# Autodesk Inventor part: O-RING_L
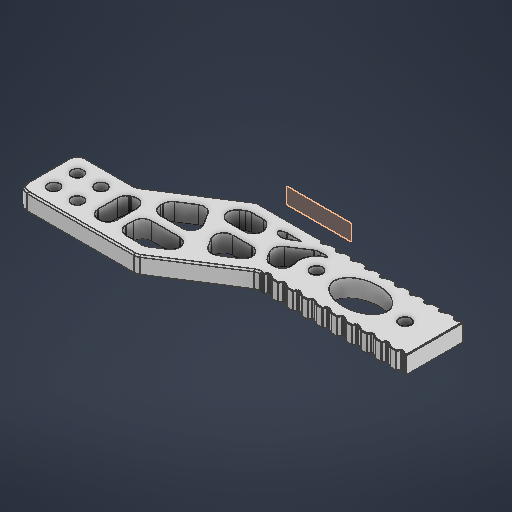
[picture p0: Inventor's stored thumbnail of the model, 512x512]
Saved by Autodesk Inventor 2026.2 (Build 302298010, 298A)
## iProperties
Created: 2026-05
Part Number: O-RING_L
Material: 일반
Document SubType Name: Modeling
Designer: work
Density: 1 g/cm^3
Appearance: 기본값
Author: work
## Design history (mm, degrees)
sketch "스케치1"
  geometry: L1 (0, 22)-(0, -22); L2 (0, -22)-(8, -22); L3 (8, -22)-(8, -30); L4 (8, -30)-(0, -30); L5 (0, -30)-(0, -22); L6 (0, -22)-(8, -30); L7 (8, -22)-(0, -30); L8 (-6, -36)-(14, -36); L9 (14, -36)-(14, -16); L10 (14, -16)-(-6, -16); L11 (-6, -16)-(-6, -36); L12 (-6, -36)-(14, -16); L13 (14, -36)-(-6, -16); L14 (-6, -16)-(-31, 0); L15 (-101, 0)-(-101, -20); L16 (-6, -36)-(-26, -36); L17 (-26, -36)-(-51, -20); L18 (0, 0)-(-31, 0); L19 (-101, -10)-(-15.375, -10); L20 (-101, 0)-(-99.268, -1); L21 (-99.268, -1)-(-98.577, -1); L22 (-98.577, -1)-(-98, 0); L23 (-93.577, -1)-(-93, 0); L24 (-94.268, -1)-(-93.577, -1); L25 (-96, 0)-(-94.268, -1); L26 (-88.577, -1)-(-88, 0); L27 (-89.268, -1)-(-88.577, -1); L28 (-91, 0)-(-89.268, -1); L29 (-83.577, -1)-(-83, 0); L30 (-84.268, -1)-(-83.577, -1); L31 (-86, 0)-(-84.268, -1); L32 (-78.577, -1)-(-78, 0); L33 (-79.268, -1)-(-78.577, -1); L34 (-81, 0)-(-79.268, -1); L35 (-73.577, -1)-(-73, 0); L36 (-74.268, -1)-(-73.577, -1); L37 (-76, 0)-(-74.268, -1); L38 (-68.577, -1)-(-68, 0); L39 (-69.268, -1)-(-68.577, -1); L40 (-71, 0)-(-69.268, -1); L41 (-63.577, -1)-(-63, 0); L42 (-64.268, -1)-(-63.577, -1); L43 (-66, 0)-(-64.268, -1); L44 (-58.577, -1)-(-58, 0); L45 (-59.268, -1)-(-58.577, -1); L46 (-61, 0)-(-59.268, -1); L47 (-53.577, -1)-(-53, 0); L48 (-54.268, -1)-(-53.577, -1); L49 (-56, 0)-(-54.268, -1); L50 (-73.577, -19)-(-73, -20); L51 (-74.268, -19)-(-73.577, -19); L52 (-76, -20)-(-74.268, -19); L53 (-78.577, -19)-(-78, -20); L54 (-79.268, -19)-(-78.577, -19); L55 (-81, -20)-(-79.268, -19); L56 (-83.577, -19)-(-83, -20); L57 (-84.268, -19)-(-83.577, -19); L58 (-86, -20)-(-84.268, -19); L59 (-71, -20)-(-69.268, -19); L60 (-69.268, -19)-(-68.577, -19); L61 (-68.577, -19)-(-68, -20); L62 (-66, -20)-(-64.268, -19); L63 (-64.268, -19)-(-63.577, -19); L64 (-63.577, -19)-(-63, -20)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; C1 r 2 at (-91, -10); C2 r 2 at (-61, -10); 48 further points; 1 other entity
  constraints: 194 end point, 39 symmetric about line, 38 horizontal alignment, 30 parallel, 26 point on line, 11 midpoint, 9 collinear, 9 horizontal, 8 perpendicular, 6 coincident, 4 vertical, 2 centre point, 17 other
  dimensions: "d0" = 44 distance of L1.start L1.end; "d1" = 8 distance of L3.end L4.end; "d2" = 8 distance of L2.end L3.end; "d3" = 6 distance between parallel lines of L2 L10; "d5" = 50 distance from line of L17.end L15; "d6" = 20 distance of L8.start L16.end; "d7" = 25 horizontal distance of L14.end L10.end; "d8" = 20 distance of L15.start L15.end; "d9" = 3 distance of L15.start L22.end; "d10" = 30 deg angle to the sketch x axis of L20; "d11" = 1 distance of the line from the sketch origin of L21; "d14" = 5 distance of L21.end L23.start; "d19" = 4 diameter of C1; "d20" = 4 diameter of C2; "d21" = 30 distance of C1.centre C2.centre; "d22" = 10 distance from line of L15 C1.centre; "d23" = 4 distance between parallel lines of L14 L80; "d24" = 4 distance between parallel lines of L16 L82; "d25" = 3 distance between parallel lines of L90 L86; "d26" = 3 distance between parallel lines of L91 L92; "d27" = 3 distance from line of point (-32.04, -15.735) L89; "d28" = 3 distance between parallel lines of L94 L93; "d29" = 3 distance between parallel lines of L87 L88; "d30" = 3 distance between parallel lines of L95 L96
  node "스케치 - 직사각형 패턴1" dims "d14" = 5, "d17" = 10
extrude "돌출1" new body sketch "스케치1" distance "d31" = 6; taper "d32" = 0 deg
hole "구멍1" sketch "스케치1" diameter "d33" = 4; stored, may be unused: countersink angle "d37" = 90 deg, drill point angle "d39" = 118 deg; dims "d34" = 6, "d35" = 6.2, "d36" = 3, "d38" = 8
sketch "스케치2"
  geometry: C1 r 2 at (61, -10) reference; C2 r 2 at (91, -10) reference; 3 further points
  constraints: 2 coincident
hole "구멍2" sketch "스케치2" at (61, -10), (91, -10) diameter "d40" = 4; stored, may be unused: countersink angle "d44" = 90 deg, drill point angle "d46" = 118 deg; dims "d41" = 6, "d42" = 6.2, "d43" = 3, "d45" = 8
fillet "모깎기1" dims "d47" = 3
fillet "모깎기2" dims "d48" = 0.2
sketch "스케치3"
  geometry: L1 (51.878, -20)-(52.378, -20); L2 (52.378, -20)-(52.378, -19.5); L3 (52.378, -19.5)-(51.878, -19.5); L4 (51.878, -19.5)-(51.878, -20); L5 (51.878, -0.5)-(52.378, -0.5); L6 (52.378, -0.5)-(52.378, 0); L7 (52.378, 0)-(51.878, 0); L8 (51.878, 0)-(51.878, -0.5); L9 (31.878, 0)-(52.885, 0) reference; L10 (52.378, -19.5)-(52.378, -0.5); A1 r 3 centre (51.878, -23) between (51.878, -20) and (50.261, -20.473) reference; 1 further point
  constraints: 18 end point, 4 parallel, 2 horizontal, 2 perpendicular, 1 point on line, 1 vertical
  dimensions: "d49" = 0.5 distance of L3.end L2.end; "d50" = 0.5 distance of L2.end L1.end; "d51" = 0.5 distance of L7.end L6.end; "d52" = 0.5 distance of L6.end L5.end
extrude "돌출2" cut sketch "스케치3" extent not by distance; stored distance "d53" = 0; taper "d54" = 0 deg
chamfer "모따기1" distance "d55" = 0.5; stored, may be unused: second distance "d56" = 2, angle "d57" = 45 deg
chamfer "모따기2" distance "d58" = 0.2; stored, may be unused: second distance "d59" = 2, angle "d60" = 45 deg
node "작업 평면1"
sketch "스케치4"
  geometry: L1 (-37.502, -103.645)-(133.146, -103.645); L2 (133.146, -103.645)-(133.146, 10.321); L3 (133.146, 10.321)-(-37.502, 10.321); L4 (-37.502, 10.321)-(-37.502, -103.645); 1 further point
  constraints: 8 end point, 2 parallel, 1 horizontal, 1 perpendicular
extrude "돌출3" cut sketch "스케치4" extent not by distance; stored distance "d62" = 0; taper "d63" = 0 deg
node "솔리드1"
mirror "미러1"
node "작업 평면2"
feature "A9D066F2-1C7D-4E18-AEED-F7BC21143FA4" dims "d33" = 4, "d34" = 6, "d35" = 6.2, "d36" = 3, "d37" = 90 deg, "d38" = 8, "d39" = 118 deg
